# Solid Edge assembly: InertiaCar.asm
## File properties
Author: there
Template: Iso Metric Assembly.asm
Last saved by: there
Revision: 13
Application: Solid Edge
Username: there
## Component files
eje2.par
Flywheel.par
eje.par
ppolea central.par
barra1.par
base.par
Ejellantas.par
PoleaGde.par
Soportes ejes.par
Llanta azul.par
dirsup.par
Support2.par
barra2.par
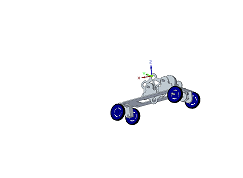
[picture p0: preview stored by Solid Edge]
